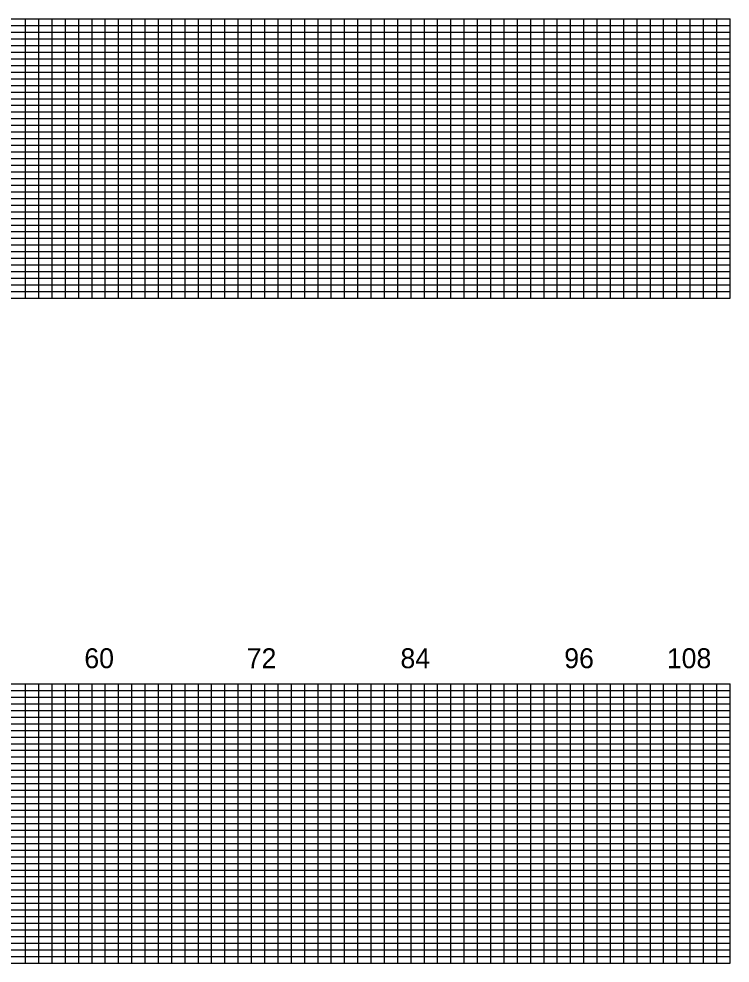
# Model space of a CAD drawing. Extents: x 1870112 to 1888282, y 758439 to 777406.
# Drawn here: x 1885607 to 1888282, y 758464 to 762014 of the extents above; entities that cross this region are included whole.
import ezdxf

# ---------------------------------------------------------------- set-up
doc = ezdxf.new("R2010")
doc.units = 0
doc.layers.add('RD_PD_WallFill', color=7, linetype='Continuous')

msp = doc.modelspace()

# ---------------------------------------------------------------- linework, layer by layer
at = {"layer": 'RD_PD_WallFill'}
for p, q in [((1882931.6, 762014.2), (1888281.6, 762014.2)), ((1885631.7, 760964.2), (1885631.6, 762014.2)), ((1885631.7, 760964.2), (1885631.6, 762014.2)), ((1885681.7, 760964.2), (1885681.6, 762014.2)), ((1885681.7, 760964.2), (1885681.6, 762014.2)), ((1885731.7, 760964.2), (1885731.6, 762014.2)), ((1885731.7, 760964.2), (1885731.6, 762014.2)), ((1885781.7, 760964.2), (1885781.6, 762014.2)), ((1885781.7, 760964.2), (1885781.6, 762014.2)), ((1885831.7, 760964.2), (1885831.6, 762014.2)), ((1885831.7, 760964.2), (1885831.6, 762014.2)), ((1885881.7, 760964.2), (1885881.7, 762014.2)), ((1885881.7, 760964.2), (1885881.7, 762014.2)), ((1885931.7, 760964.2), (1885931.7, 762014.2)), ((1885931.7, 760964.2), (1885931.7, 762014.2)), ((1885981.7, 760964.2), (1885981.7, 762014.2)), ((1885981.7, 760964.2), (1885981.7, 762014.2)), ((1886031.7, 760964.2), (1886031.7, 762014.2)), ((1886031.7, 760964.2), (1886031.7, 762014.2)), ((1886081.7, 760964.2), (1886081.7, 762014.2)), ((1886081.7, 760964.2), (1886081.7, 762014.2)), ((1886131.7, 760964.2), (1886131.7, 762014.2)), ((1886131.7, 760964.2), (1886131.7, 762014.2)), ((1886181.7, 760964.2), (1886181.7, 762014.2)), ((1886181.7, 760964.2), (1886181.7, 762014.2)), ((1886231.7, 760964.2), (1886231.7, 762014.2)), ((1886231.7, 760964.2), (1886231.7, 762014.2)), ((1886281.7, 760964.2), (1886281.7, 762014.2)), ((1886281.7, 760964.2), (1886281.7, 762014.2)), ((1886331.6, 760964.2), (1886331.7, 762014.2)), ((1886331.6, 760964.2), (1886331.7, 762014.2)), ((1886381.7, 760964.2), (1886381.7, 762014.2)), ((1886381.7, 760964.2), (1886381.7, 762014.2)), ((1886431.7, 760964.2), (1886431.7, 762014.2)), ((1886431.7, 760964.2), (1886431.7, 762014.2)), ((1886481.6, 760964.2), (1886481.7, 762014.2)), ((1886481.6, 760964.2), (1886481.7, 762014.2)), ((1886531.6, 760964.2), (1886531.7, 762014.2)), ((1886531.6, 760964.2), (1886531.7, 762014.2)), ((1886581.7, 760964.2), (1886581.7, 762014.2)), ((1886581.7, 760964.2), (1886581.7, 762014.2)), ((1886631.7, 760964.2), (1886631.7, 762014.2)), ((1886631.7, 760964.2), (1886631.7, 762014.2)), ((1886681.7, 760964.2), (1886681.7, 762014.2)), ((1886681.7, 760964.2), (1886681.7, 762014.2)), ((1886731.7, 760964.2), (1886731.7, 762014.2)), ((1886731.7, 760964.2), (1886731.7, 762014.2)), ((1886781.7, 760964.2), (1886781.7, 762014.2)), ((1886781.7, 760964.2), (1886781.7, 762014.2)), ((1886831.7, 760964.2), (1886831.7, 762014.2)), ((1886831.7, 760964.2), (1886831.7, 762014.2)), ((1886881.7, 760964.2), (1886881.7, 762014.2)), ((1886881.7, 760964.2), (1886881.7, 762014.2)), ((1886931.7, 760964.2), (1886931.7, 762014.2)), ((1886931.7, 760964.2), (1886931.7, 762014.2)), ((1886981.7, 760964.2), (1886981.7, 762014.2)), ((1886981.7, 760964.2), (1886981.7, 762014.2)), ((1887031.7, 760964.2), (1887031.7, 762014.2)), ((1887031.7, 760964.2), (1887031.7, 762014.2)), ((1887081.7, 760964.2), (1887081.7, 762014.2)), ((1887081.7, 760964.2), (1887081.7, 762014.2)), ((1887131.7, 760964.2), (1887131.7, 762014.2)), ((1887131.7, 760964.2), (1887131.7, 762014.2)), ((1887181.7, 760964.2), (1887181.7, 762014.2)), ((1887181.7, 760964.2), (1887181.7, 762014.2)), ((1887231.7, 760964.2), (1887231.7, 762014.2)), ((1887231.7, 760964.2), (1887231.7, 762014.2)), ((1887281.7, 760964.2), (1887281.7, 762014.2)), ((1887281.7, 760964.2), (1887281.7, 762014.2)), ((1887331.7, 760964.2), (1887331.7, 762014.2)), ((1887331.7, 760964.2), (1887331.7, 762014.2)), ((1887381.7, 760964.2), (1887381.7, 762014.2)), ((1887381.7, 760964.2), (1887381.7, 762014.2)), ((1887431.7, 760964.2), (1887431.7, 762014.2)), ((1887431.7, 760964.2), (1887431.7, 762014.2)), ((1887481.7, 760964.2), (1887481.7, 762014.2)), ((1887481.7, 760964.2), (1887481.7, 762014.2)), ((1887531.7, 760964.2), (1887531.7, 762014.2)), ((1887531.7, 760964.2), (1887531.7, 762014.2)), ((1887581.7, 760964.2), (1887581.7, 762014.2)), ((1887581.7, 760964.2), (1887581.7, 762014.2)), ((1887631.7, 760964.2), (1887631.7, 762014.2)), ((1887631.7, 760964.2), (1887631.7, 762014.2)), ((1887681.7, 760964.2), (1887681.7, 762014.2)), ((1887681.7, 760964.2), (1887681.7, 762014.2)), ((1887731.7, 760964.2), (1887731.7, 762014.2)), ((1887731.7, 760964.2), (1887731.7, 762014.2)), ((1887781.7, 760964.2), (1887781.7, 762014.2)), ((1887781.7, 760964.2), (1887781.7, 762014.2)), ((1887831.7, 760964.2), (1887831.7, 762014.2)), ((1887831.7, 760964.2), (1887831.7, 762014.2)), ((1887881.7, 760964.2), (1887881.7, 762014.2)), ((1887881.7, 760964.2), (1887881.7, 762014.2)), ((1887931.7, 760964.2), (1887931.7, 762014.2)), ((1887931.7, 760964.2), (1887931.7, 762014.2)), ((1887981.7, 760964.2), (1887981.7, 762014.2)), ((1887981.7, 760964.2), (1887981.7, 762014.2)), ((1888031.7, 760964.2), (1888031.7, 762014.2)), ((1888031.7, 760964.2), (1888031.7, 762014.2)), ((1888081.7, 760964.2), (1888081.7, 762014.2)), ((1888081.7, 760964.2), (1888081.7, 762014.2)), ((1888131.7, 760964.2), (1888131.7, 762014.2)), ((1888131.7, 760964.2), (1888131.7, 762014.2)), ((1888181.7, 760964.2), (1888181.7, 762014.2)), ((1888181.7, 760964.2), (1888181.7, 762014.2)), ((1888231.7, 760964.2), (1888231.7, 762014.2)), ((1888231.7, 760964.2), (1888231.7, 762014.2)), ((1888281.7, 760964.2), (1888281.7, 762014.2)), ((1888281.7, 760964.2), (1888281.7, 762014.2)), ((1883381.6, 761989.2), (1888281.6, 761989.2)), ((1883381.6, 761989.2), (1888281.6, 761989.2)), ((1883381.6, 761964.2), (1888281.6, 761964.2)), ((1883381.6, 761939.2), (1888281.6, 761939.2)), ((1883381.6, 761914.2), (1888281.6, 761914.2)), ((1883381.6, 761889.2), (1888281.6, 761889.2)), ((1882931.6, 761864.2), (1888281.6, 761864.2)), ((1882931.6, 761839.2), (1888281.6, 761839.2)), ((1882931.6, 761814.2), (1888281.6, 761814.2)), ((1882931.6, 761789.2), (1888281.6, 761789.2)), ((1882931.6, 761764.2), (1888281.6, 761764.2)), ((1882931.6, 761739.2), (1888281.6, 761739.2)), ((1882931.6, 761714.2), (1888281.6, 761714.2)), ((1882931.6, 761689.2), (1888281.6, 761689.2)), ((1882931.6, 761664.2), (1888281.6, 761664.2)), ((1882931.6, 761639.2), (1888281.6, 761639.2)), ((1882931.6, 761614.2), (1888281.6, 761614.2)), ((1882931.6, 761589.2), (1888281.6, 761589.2)), ((1882931.6, 761564.2), (1888281.6, 761564.2)), ((1882931.6, 761539.2), (1888281.6, 761539.2)), ((1882931.6, 761514.2), (1888281.6, 761514.2)), ((1882931.6, 761489.2), (1888281.6, 761489.2)), ((1882931.6, 761464.2), (1888281.6, 761464.2)), ((1882931.6, 761439.2), (1888281.6, 761439.2)), ((1882931.6, 761414.2), (1888281.6, 761414.2)), ((1882931.6, 761389.2), (1888281.6, 761389.2)), ((1882931.6, 761364.2), (1888281.6, 761364.2)), ((1882931.6, 761339.2), (1888281.6, 761339.2)), ((1882931.6, 761314.2), (1888281.6, 761314.2)), ((1882931.6, 761289.2), (1888281.6, 761289.2)), ((1882931.6, 761264.2), (1888281.6, 761264.2)), ((1882931.6, 761239.2), (1888281.6, 761239.2)), ((1882931.6, 761214.2), (1888281.6, 761214.2)), ((1882931.6, 761189.2), (1888281.6, 761189.2)), ((1882931.6, 761164.2), (1888281.6, 761164.2)), ((1882931.6, 761139.2), (1888281.6, 761139.2)), ((1882931.6, 761114.2), (1888281.6, 761114.2)), ((1882931.6, 761089.2), (1888281.6, 761089.2)), ((1882931.6, 761064.2), (1888281.6, 761064.2)), ((1882931.6, 761039.2), (1888281.6, 761039.2)), ((1882931.6, 761014.2), (1888281.6, 761014.2)), ((1882931.6, 760989.2), (1888281.6, 760989.2)), ((1882931.6, 760964.2), (1888281.6, 760964.2)), ((1882931.6, 760964.2), (1888281.6, 760964.2)), ((1882931.6, 759514.2), (1888281.6, 759514.2)), ((1885631.7, 758464.2), (1885631.6, 759514.2)), ((1885631.7, 758464.2), (1885631.6, 759514.2)), ((1885681.7, 758464.2), (1885681.6, 759514.2)), ((1885681.7, 758464.2), (1885681.6, 759514.2)), ((1885731.7, 758464.2), (1885731.6, 759514.2)), ((1885731.7, 758464.2), (1885731.6, 759514.2)), ((1885781.7, 758464.2), (1885781.6, 759514.2)), ((1885781.7, 758464.2), (1885781.6, 759514.2)), ((1885831.7, 758464.2), (1885831.6, 759514.2)), ((1885831.7, 758464.2), (1885831.6, 759514.2)), ((1885881.7, 758464.2), (1885881.7, 759514.2)), ((1885881.7, 758464.2), (1885881.7, 759514.2)), ((1885931.7, 758464.2), (1885931.7, 759514.2)), ((1885931.7, 758464.2), (1885931.7, 759514.2)), ((1885981.7, 758464.2), (1885981.7, 759514.2)), ((1885981.7, 758464.2), (1885981.7, 759514.2)), ((1886031.7, 758464.2), (1886031.7, 759514.2)), ((1886031.7, 758464.2), (1886031.7, 759514.2)), ((1886081.7, 758464.2), (1886081.7, 759514.2)), ((1886081.7, 758464.2), (1886081.7, 759514.2)), ((1886131.7, 758464.2), (1886131.7, 759514.2)), ((1886131.7, 758464.2), (1886131.7, 759514.2)), ((1886181.7, 758464.2), (1886181.7, 759514.2)), ((1886181.7, 758464.2), (1886181.7, 759514.2)), ((1886231.7, 758464.2), (1886231.7, 759514.2)), ((1886231.7, 758464.2), (1886231.7, 759514.2)), ((1886281.7, 758464.2), (1886281.7, 759514.2)), ((1886281.7, 758464.2), (1886281.7, 759514.2)), ((1886331.6, 758464.2), (1886331.7, 759514.2)), ((1886331.6, 758464.2), (1886331.7, 759514.2)), ((1886381.7, 758464.2), (1886381.7, 759514.2)), ((1886381.7, 758464.2), (1886381.7, 759514.2)), ((1886431.7, 758464.2), (1886431.7, 759514.2)), ((1886431.7, 758464.2), (1886431.7, 759514.2)), ((1886481.6, 758464.2), (1886481.7, 759514.2)), ((1886481.6, 758464.2), (1886481.7, 759514.2)), ((1886531.6, 758464.2), (1886531.7, 759514.2)), ((1886531.6, 758464.2), (1886531.7, 759514.2)), ((1886581.7, 758464.2), (1886581.7, 759514.2)), ((1886581.7, 758464.2), (1886581.7, 759514.2)), ((1886631.7, 758464.2), (1886631.7, 759514.2)), ((1886631.7, 758464.2), (1886631.7, 759514.2)), ((1886681.7, 758464.2), (1886681.7, 759514.2)), ((1886681.7, 758464.2), (1886681.7, 759514.2)), ((1886731.7, 758464.2), (1886731.7, 759514.2)), ((1886731.7, 758464.2), (1886731.7, 759514.2)), ((1886781.7, 758464.2), (1886781.7, 759514.2)), ((1886781.7, 758464.2), (1886781.7, 759514.2)), ((1886831.7, 758464.2), (1886831.7, 759514.2)), ((1886831.7, 758464.2), (1886831.7, 759514.2)), ((1886881.7, 758464.2), (1886881.7, 759514.2)), ((1886881.7, 758464.2), (1886881.7, 759514.2)), ((1886931.7, 758464.2), (1886931.7, 759514.2)), ((1886931.7, 758464.2), (1886931.7, 759514.2)), ((1886981.7, 758464.2), (1886981.7, 759514.2)), ((1886981.7, 758464.2), (1886981.7, 759514.2)), ((1887031.7, 758464.2), (1887031.7, 759514.2)), ((1887031.7, 758464.2), (1887031.7, 759514.2)), ((1887081.7, 758464.2), (1887081.7, 759514.2)), ((1887081.7, 758464.2), (1887081.7, 759514.2)), ((1887131.7, 758464.2), (1887131.7, 759514.2)), ((1887131.7, 758464.2), (1887131.7, 759514.2)), ((1887181.7, 758464.2), (1887181.7, 759514.2)), ((1887181.7, 758464.2), (1887181.7, 759514.2)), ((1887231.7, 758464.2), (1887231.7, 759514.2)), ((1887231.7, 758464.2), (1887231.7, 759514.2)), ((1887281.7, 758464.2), (1887281.7, 759514.2)), ((1887281.7, 758464.2), (1887281.7, 759514.2)), ((1887331.7, 758464.2), (1887331.7, 759514.2)), ((1887331.7, 758464.2), (1887331.7, 759514.2)), ((1887381.7, 758464.2), (1887381.7, 759514.2)), ((1887381.7, 758464.2), (1887381.7, 759514.2)), ((1887431.7, 758464.2), (1887431.7, 759514.2)), ((1887431.7, 758464.2), (1887431.7, 759514.2)), ((1887481.7, 758464.2), (1887481.7, 759514.2)), ((1887481.7, 758464.2), (1887481.7, 759514.2)), ((1887531.7, 758464.2), (1887531.7, 759514.2)), ((1887531.7, 758464.2), (1887531.7, 759514.2)), ((1887581.7, 758464.2), (1887581.7, 759514.2)), ((1887581.7, 758464.2), (1887581.7, 759514.2)), ((1887631.7, 758464.2), (1887631.7, 759514.2)), ((1887631.7, 758464.2), (1887631.7, 759514.2)), ((1887681.7, 758464.2), (1887681.7, 759514.2)), ((1887681.7, 758464.2), (1887681.7, 759514.2)), ((1887731.7, 758464.2), (1887731.7, 759514.2)), ((1887731.7, 758464.2), (1887731.7, 759514.2)), ((1887781.7, 758464.2), (1887781.7, 759514.2)), ((1887781.7, 758464.2), (1887781.7, 759514.2)), ((1887831.7, 758464.2), (1887831.7, 759514.2)), ((1887831.7, 758464.2), (1887831.7, 759514.2)), ((1887881.7, 758464.2), (1887881.7, 759514.2)), ((1887881.7, 758464.2), (1887881.7, 759514.2)), ((1887931.7, 758464.2), (1887931.7, 759514.2)), ((1887931.7, 758464.2), (1887931.7, 759514.2)), ((1887981.7, 758464.2), (1887981.7, 759514.2)), ((1887981.7, 758464.2), (1887981.7, 759514.2)), ((1888031.7, 758464.2), (1888031.7, 759514.2)), ((1888031.7, 758464.2), (1888031.7, 759514.2)), ((1888081.7, 758464.2), (1888081.7, 759514.2)), ((1888081.7, 758464.2), (1888081.7, 759514.2)), ((1888131.7, 758464.2), (1888131.7, 759514.2)), ((1888131.7, 758464.2), (1888131.7, 759514.2)), ((1888181.7, 758464.2), (1888181.7, 759514.2)), ((1888181.7, 758464.2), (1888181.7, 759514.2)), ((1888231.7, 758464.2), (1888231.7, 759514.2)), ((1888231.7, 758464.2), (1888231.7, 759514.2)), ((1888281.7, 758464.2), (1888281.7, 759514.2)), ((1888281.7, 758464.2), (1888281.7, 759514.2)), ((1883381.6, 759489.2), (1888281.6, 759489.2)), ((1883381.6, 759489.2), (1888281.6, 759489.2)), ((1883381.6, 759464.2), (1888281.6, 759464.2)), ((1883381.6, 759439.2), (1888281.6, 759439.2)), ((1883381.6, 759414.2), (1888281.6, 759414.2)), ((1883381.6, 759389.2), (1888281.6, 759389.2)), ((1882931.6, 759364.2), (1888281.6, 759364.2)), ((1882931.6, 759339.2), (1888281.6, 759339.2)), ((1882931.6, 759314.2), (1888281.6, 759314.2)), ((1882931.6, 759289.2), (1888281.6, 759289.2)), ((1882931.6, 759264.2), (1888281.6, 759264.2)), ((1882931.6, 759239.2), (1888281.6, 759239.2)), ((1882931.6, 759214.2), (1888281.6, 759214.2)), ((1882931.6, 759189.2), (1888281.6, 759189.2)), ((1882931.6, 759164.2), (1888281.6, 759164.2)), ((1882931.6, 759139.2), (1888281.6, 759139.2)), ((1882931.6, 759114.2), (1888281.6, 759114.2)), ((1882931.6, 759089.2), (1888281.6, 759089.2)), ((1882931.6, 759064.2), (1888281.6, 759064.2)), ((1882931.6, 759039.2), (1888281.6, 759039.2)), ((1882931.6, 759014.2), (1888281.6, 759014.2)), ((1882931.6, 758989.2), (1888281.6, 758989.2)), ((1882931.6, 758964.2), (1888281.6, 758964.2)), ((1882931.6, 758939.2), (1888281.6, 758939.2)), ((1882931.6, 758914.2), (1888281.6, 758914.2)), ((1882931.6, 758889.2), (1888281.6, 758889.2)), ((1882931.6, 758864.2), (1888281.6, 758864.2)), ((1882931.6, 758839.2), (1888281.6, 758839.2)), ((1882931.6, 758814.2), (1888281.6, 758814.2)), ((1882931.6, 758789.2), (1888281.6, 758789.2)), ((1882931.6, 758764.2), (1888281.6, 758764.2)), ((1882931.6, 758739.2), (1888281.6, 758739.2)), ((1882931.6, 758714.2), (1888281.6, 758714.2)), ((1882931.6, 758689.2), (1888281.6, 758689.2)), ((1882931.6, 758664.2), (1888281.6, 758664.2)), ((1882931.6, 758639.2), (1888281.6, 758639.2)), ((1882931.6, 758614.2), (1888281.6, 758614.2)), ((1882931.6, 758589.2), (1888281.6, 758589.2)), ((1882931.6, 758564.2), (1888281.6, 758564.2)), ((1882931.6, 758539.2), (1888281.6, 758539.2)), ((1882931.6, 758514.2), (1888281.6, 758514.2)), ((1882931.6, 758489.2), (1888281.6, 758489.2)), ((1882931.6, 758464.2), (1888281.6, 758464.2)), ((1882931.6, 758464.2), (1888281.6, 758464.2))]:
    msp.add_line(p, q, dxfattribs=at)

# ---------------------------------------------------------------- texts
for s, p in [('60', (1885852.8, 759572.9)), ('60', (1885852.8, 759572.9)), ('72', (1886463.5, 759572.9)), ('72', (1886463.5, 759572.9)), ('84', (1887041.7, 759572.9)), ('84', (1887041.7, 759572.9)), ('96', (1887657.8, 759572.9)), ('96', (1887657.8, 759572.9)), ('108', (1888043.6, 759572.9))]:
    msp.add_text(s, height=75, dxfattribs=at).set_placement(p)

doc.saveas('drawing.dxf')
